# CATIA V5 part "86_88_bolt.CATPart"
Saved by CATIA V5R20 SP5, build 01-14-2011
Part number: 86_88_bolt
Bounding box of the stored display mesh (mm): x -11 to 11, y 22.409 to 44.315, z -180.5 to -159.5
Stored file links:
  C:\Documents and Settings\anizard\Bureau\13\86_88_bolt.CATPart
  C:\Documents and Settings\anizard\Bureau\13\anizard.CATProduct
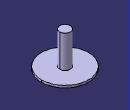
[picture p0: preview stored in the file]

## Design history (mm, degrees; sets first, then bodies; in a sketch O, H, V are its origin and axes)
Set1
  Line1: linked copy from another document
  Plane1: linked copy from another document
Body1 (main body)
  Sketch1 on Plane1, origin (0, 0, -174.5), H (1, 0, 0), V (0, -1, 0)
    circle A1 centre (0, -33.3619) radius 2.5
    point P1 (0, -33.3619)
    reference projected point E1 (0, -33.3619) from Line1
    radius A1 = 2.5
    coincidence: E1 P1
  Pad1: profile Sketch1, direction (0, 0, 1), length 15
  Sketch2 on start face of Pad1, origin (0, 0, -174.5), H (1, 0, 0), V (0, -1, 0)
    circle A1 centre (0, -33.3619) radius 11
    reference projected circle E1 centre (0, -33.3619) radius 2.5 from edge [face of Pad1 from Sketch1.A1 | start face of Pad1]
    radius A1 = 11
    concentricity: A1 E1
  Pad2: profile Sketch2, direction (0, 0, -1), length 1
  Sketch3 on end face of Pad2, origin (0, 0, -175.5), H (1, 0, 0), V (0, -1, 0)
    circle A1 centre (0, -33.3619) radius 4.25
    reference projected circle E1 centre (0, -33.3619) radius 11 from edge [face of Pad2 from Sketch2.A1 | end face of Pad2]
    radius A1 = 4.25
    concentricity: E1 A1
  Pad3: profile Sketch3, direction (0, 0, -1), length 5
  Sketch4 on end face of Pad3, origin (0, 0, -180.5), H (1, 0, 0), V (0, -1, 0)
    point P1 (0, -33.3619)
    point P2 (1.1547, -35.3619)
    point P3 (2.3094, -33.3619)
    point P4 (1.1547, -31.3619)
    point P5 (-1.1547, -31.3619)
    point P6 (-2.3094, -33.3619)
    point P7 (-1.1547, -35.3619)
    point P8 (1.732, -34.3619)
    line L1 (1.1547, -35.3619) -> (2.3094, -33.3619)
    line L2 (2.3094, -33.3619) -> (1.1547, -31.3619)
    line L3 (1.1547, -31.3619) -> (-1.1547, -31.3619)
    line L4 (-1.1547, -31.3619) -> (-2.3094, -33.3619)
    line L5 (-2.3094, -33.3619) -> (-1.1547, -35.3619)
    line L6 (-1.1547, -35.3619) -> (1.1547, -35.3619)
    construction line L7 (0, -33.3619) -> (1.732, -34.3619)
    construction circle A1 centre (0, -33.3619) radius 2.3094
    construction arc A2 centre (-2.3094, -33.3619) radius 2.3094 from (-1.1547, -31.3619) to (-1.1547, -35.3619) cw
    construction arc A3 centre (2.3094, -33.3619) radius 2.3094 from (1.1547, -31.3619) to (1.1547, -35.3619) ccw
    reference projected circle E1 centre (0, -33.3619) radius 4.25 from edge [face of Pad3 from Sketch3.A1 | end face of Pad3]
    distance L5 L2 = 4
    coincidence: A1 P2, A1 P3, A1 P4, A1 P5, A1 P6, A1 P7, A2 P1, A3 P1
    midpoint: P8 L1
    parallelism: L1 L4
    concentricity: A1 E1
    horizontal: L3 H
  Pocket1: profile Sketch4, direction (0, 0, 1), length 4
  Fillet1: radius 0.5, on edge [face of Pad3 from Sketch3.A1 | end face of Pad3]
